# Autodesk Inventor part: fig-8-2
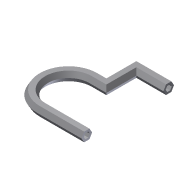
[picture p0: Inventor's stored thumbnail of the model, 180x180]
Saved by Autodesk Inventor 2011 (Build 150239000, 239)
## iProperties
Created: 2004-05
Part Number: fig-8-2
Document SubType Name: Modeling
Designer: CADCIM Technologies
Manufacturer: Standard
Standards Organization: Custom
Density: 1 g/cm^3
Author: CADCIM Technologies
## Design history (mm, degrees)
sketch "Sketch1"
  geometry: L1 (-42.583, 3.219)-(-90.066, 3.219); L2 (-90.066, 58.92)-(-77.282, 58.92); L3 (-77.282, 58.92)-(-77.282, 91.063); L4 (-77.282, 91.063)-(-42.583, 91.063); A1 r 27.851 centre (-90.066, 31.07) between (-90.066, 58.92) and (-90.066, 3.219)
  constraints: 8 end point, 2 parallel, 2 point on circle, 2 tangent, 1 centre point, 1 perpendicular
workplane "Work Plane2"
sketch "Sketch5"
  geometry: L1 (-5.697, 0)-(-2.849, 4.934); L2 (-2.849, 4.934)-(2.849, 4.934); L3 (2.849, 4.934)-(5.697, 0); L4 (5.697, 0)-(2.849, -4.934); L5 (2.849, -4.934)-(-2.849, -4.934); L6 (-2.849, -4.934)-(-5.697, 0); L7 (-3.256, 0)-(-1.628, 2.819); L8 (-1.628, 2.819)-(1.628, 2.819); L9 (1.628, 2.819)-(3.256, 0); L10 (3.256, 0)-(1.628, -2.819); L11 (1.628, -2.819)-(-1.628, -2.819); L12 (-1.628, -2.819)-(-3.256, 0); 2 further points
  constraints: 24 end point, 1 coincident, 22 other
sweep "Sweep4" sketch "Sketch5" dims "d3" = 0
body "Solid1"
